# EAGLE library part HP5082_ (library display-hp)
LED DISPLAY + - 1/2 character dot matrix, decimal point right
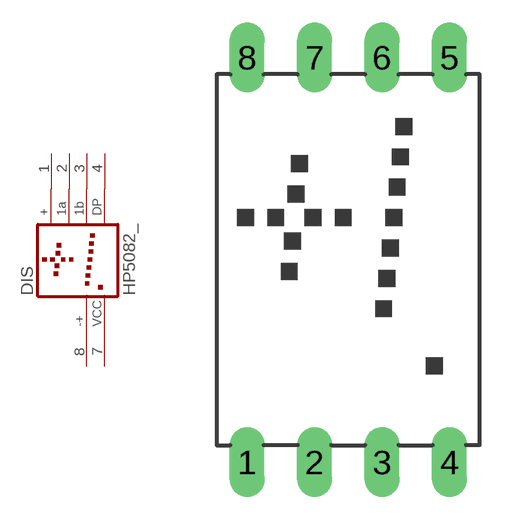
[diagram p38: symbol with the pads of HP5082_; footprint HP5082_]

Designator prefix DIS

## HP5082_ (OC_FARNELL: unknown; OC_NEWARK: unknown)  [HP5082_]
1  +  pas
2  1A  pas
3  1B  pas
4  DP  pas
7  VCC  pwr
8  -+  pas

## Footprint HP5082_ (pad centres in mm)
LED DISPLAY 8-mm + - 1/2 character dot matrix, decimal point right
drill 0.813 long: 1 -3.81,-7.62; 2 -1.27,-7.62; 3 1.27,-7.62; 4 3.81,-7.62; 5 3.81,7.62; 6 1.27,7.62; 7 -1.27,7.62; 8 -3.81,7.62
